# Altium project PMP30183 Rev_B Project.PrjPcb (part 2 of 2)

## Sheet PMP30183 Rev_B 2-Switch Forward Schematic.SchDoc: 2-Switch Forward
size 431 x 279 mm; Date: Not shown in title block; ApprovedBy: Not shown in title block; CheckedBy: Not shown in title block; Author: Not shown in title block; CompanyName: Not shown in title block; DrawnBy: R. Scibilia; Engineer: Not shown in title block; Organization: Not shown in title block; Address1: Not shown in title block; Address2: Not shown in title block; Address3: Not shown in title block; Address4: Not shown in title block; DocumentNumber: 1; Revision: Use project parameter SCH_Rev; SheetNumber: 2; SheetTotal: 2; PageSetup: Record=PageOptions¦CenterHorizontal=True¦CenterVertical=True¦PrintScale=1.00¦XCorrection=1.00¦YCorrection=1.00¦PrintKind=0¦BorderSize=5000000¦LeftOffset=0¦BottomOffset=0¦Orientation=2¦PaperLength=1000¦PaperWidth=1000¦Scale=100¦PaperSource=15¦PrintQuality=600¦MediaType=1¦DitherType=10¦PaperKind=Letter¦PrintScaleMode=1
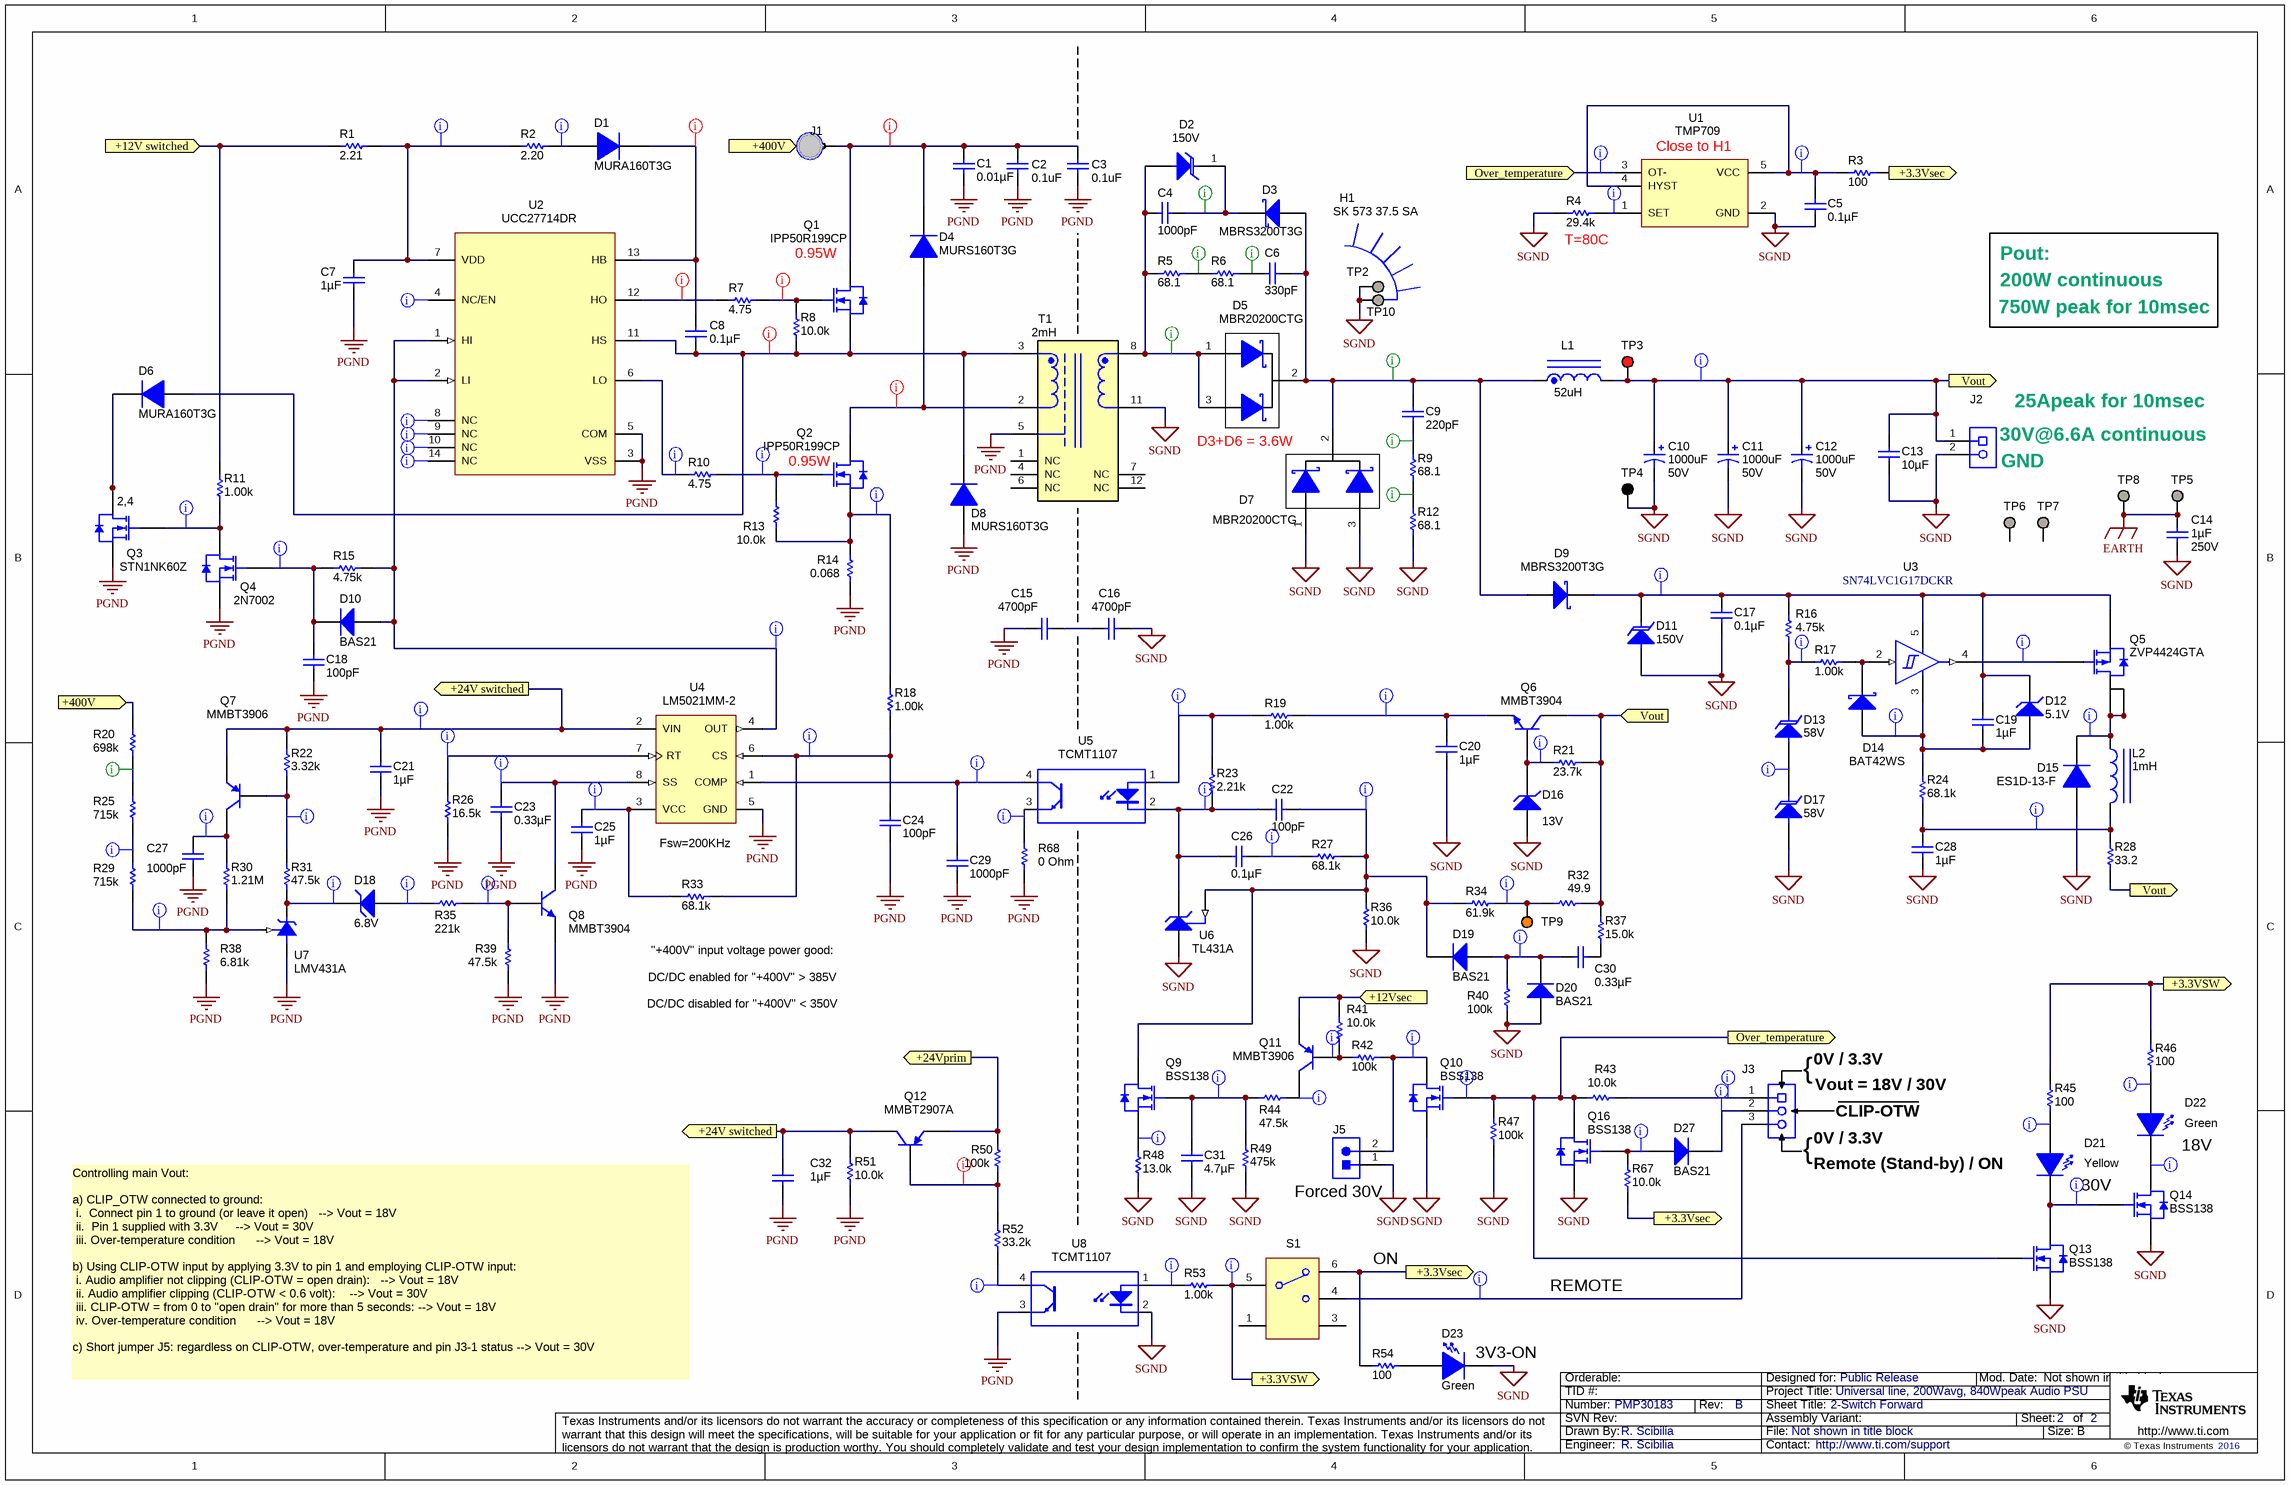
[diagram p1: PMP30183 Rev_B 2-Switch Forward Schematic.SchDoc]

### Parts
C1  ValueDisplayed: 0.01µF  [1206]  (hidden comment: C3216X7R2J103K)
C2  value 0.1uF  [1210]  (hidden comment: C3225X7T2J104K160AC)
C3  value 0.1uF  [1210]  (hidden comment: C3225X7T2J104K160AC)
C4  ValueDisplayed: 1000pF  [0805_HV]  (hidden comment: C0805C102JBRACTU)
C5  ValueDisplayed: 0.1µF  [0603]  (hidden comment: C1608X7R1H104K)
C6  ValueDisplayed: 330pF  [0603]  (hidden comment: GRM188R72E331KW07D)
C7  ValueDisplayed: 1µF  [0603]  (hidden comment: GRM188R71E105KA12D)
C8  ValueDisplayed: 0.1µF  [0603]  (hidden comment: C1608X7R1H104K)
C9  ValueDisplayed: 220pF  [1206]  (hidden comment: C3216C0G2J221J)
C10  value 1000uF  Value2: 50V  [CAPPR750W80D1600H3000]  (hidden comment: EKZM500ELL102ML25S)
C11  value 1000uF  Value2: 50V  [CAPPR750W80D1600H3000]  (hidden comment: EKZM500ELL102ML25S)
C12  value 1000uF  Value2: 50V  [CAPPR750W80D1600H3000]  (hidden comment: EKZM500ELL102ML25S)
C13  ValueDisplayed: 10µF  [1210_280]  (hidden comment: C3225X7R1H106M250AC)
C14  ValueDisplayed: 1µF  Value2: 250V  [2220_200]  (hidden comment: GRM55DR72E105KW01L)
C15  ValueDisplayed: 4700pF  [VY2_1250x500x1650]  (hidden comment: VY2472M49Y5US63V7)
C16  ValueDisplayed: 4700pF  [VY2_1250x500x1650]  (hidden comment: VY2472M49Y5US63V7)
C17  ValueDisplayed: 0.1µF  [1812]  (hidden comment: C1812C104KARACTU)
C18  ValueDisplayed: 100pF  [0603]  (hidden comment: C1608C0G1H101J)
C19  ValueDisplayed: 1µF  [0603]  (hidden comment: C1608X7R1E105K080AB)
C20  ValueDisplayed: 1µF  [0603]  (hidden comment: GRM188R71E105KA12D)
C21  ValueDisplayed: 1µF  [0805_HV]  (hidden comment: 885012207103)
C22  ValueDisplayed: 100pF  [0603]  (hidden comment: C1608C0G1H101J)
C23  ValueDisplayed: 0.33µF  [0603]  (hidden comment: C0603C334K4RACTU)
C24  ValueDisplayed: 100pF  [0603]  (hidden comment: C1608C0G1H101J)
C25  ValueDisplayed: 1µF  [0603]  (hidden comment: GRM188R71E105KA12D)
C26  ValueDisplayed: 0.1µF  [0603]  (hidden comment: C1608X7R1H104K)
C27  ValueDisplayed: 1000pF  [0603]  (hidden comment: GRM188R71H102KA01D)
C28  ValueDisplayed: 1µF  [0805_HV]  (hidden comment: 885012207103)
C29  ValueDisplayed: 1000pF  [0603]  (hidden comment: C1608X8R1H102K)
C30  ValueDisplayed: 0.33µF  [0805_HV]  (hidden comment: GRM219R71H334KA88D)
C31  ValueDisplayed: 4.7µF  [0805_HV]  (hidden comment: C2012X7R1E474K125AA)
C32  ValueDisplayed: 1µF  [0603]  (hidden comment: C1608X7R1E105K080AB)
D1  MURA160T3G  [SMA]
D2  value 150V  [SMB]  (hidden comment: SMBJ150A-13-F)
D3  MBRS3200T3G  [SMB]
D4  MURS160T3G  [SMB]
D5  MBR20200CTG  [TO-220AB]
D6  MURA160T3G  [SMA]
D7  MBR20200CTG  [TO-220AB]
D8  MURS160T3G  [SMB]
D9  MBRS3200T3G  [SMB]
D10  value BAS21  [SOT-23]  (hidden comment: BAS21-7-F)
D11  value 150V  [SMB]  (hidden comment: SMBJ150A-13-F)
D12  value 5.1V  [SOD-523]  (hidden comment: BZT52C5V1T-7)
D13  value 58V  [SMA]  (hidden comment: SMAJ58A)
D14  value BAT42WS  [sod-323]  (hidden comment: BAT42WS-7-F)
D15  ES1D-13-F  [SMA]
D16  value 13V  [sod-323]  (hidden comment: MMSZ5243BS-7-F)
D17  value 58V  [SMA]  (hidden comment: SMAJ58A)
D18  value 6.8V  [SOD-523]  (hidden comment: BZT52C6V8T-7)
D19  value BAS21  [SOT-23]  (hidden comment: BAS21-7-F)
D20  value BAS21  [SOT-23]  (hidden comment: BAS21-7-F)
D21  value Yellow  [LED_LTST-C170]  (hidden comment: LTST-C170KSKT)
D22  value Green  [LTST-C170KGKT_Green]  (hidden comment: LTST-C170KGKT)
D23  value Green  [LTST-C170KGKT_Green]  (hidden comment: LTST-C170KGKT)
D27  value BAS21  [SOT-23]  (hidden comment: BAS21-7-F)
H1  SK 573 37.5 SA  [FE_SK573_37_5]
J1  923345-01-C  [3M_923345-01-C]  (value not drawn)
J2  1732720  [Phoenix_1732720]  (value not drawn)
J3  39357-0003  [Molex_39357-0003]  (value not drawn)
J5  0022284023  [Molex_0022284023]  (value not drawn)
L1  value 52uH  [750315814]  (hidden comment: 750315814r01)
L2  ValueDisplayed: 1mH  [WE-PD_1280]  (hidden comment: 74477030)
Q1  IPP50R199CP  [TO-220AB]
Q2  IPP50R199CP  [TO-220AB]
Q3  STN1NK60Z  [SOT-223]
Q4  value 2N7002  [SOT-23]  (hidden comment: 2N7002E-T1-E3)
Q5  ZVP4424GTA  [SOT-223]
Q6  MMBT3904  [SOT-23]
Q7  MMBT3906  [SOT-23]
Q8  MMBT3904  [SOT-23]
Q9  BSS138  [SOT-23]
Q10  BSS138  [SOT-23]
Q11  MMBT3906  [SOT-23]
Q12  MMBT2907A  [SOT-23]
Q13  BSS138  [SOT-23]
Q14  BSS138  [SOT-23]
Q16  BSS138  [SOT-23]
R1  ValueDisplayed: 2.21  [0805_HV]  (hidden comment: CRCW08052R21FKEA)
R2  value 2.20  [1206]  (hidden comment: RC1206FR-072R2L)
R3  ValueDisplayed: 100  [0603]  (hidden comment: CRCW0603100RFKEA)
R4  ValueDisplayed: 29.4k  [0603]  (hidden comment: CRCW060329K4FKEA)
R5  ValueDisplayed: 68.1  [2512]  (hidden comment: CRCW251268R1FKEG)
R6  ValueDisplayed: 68.1  [2512]  (hidden comment: CRCW251268R1FKEG)
R7  ValueDisplayed: 4.75  [0805_HV]  (hidden comment: RC0805FR-074R75L)
R8  value 10.0k  [0603]  (hidden comment: CRCW060310K0FKEA)
R9  ValueDisplayed: 68.1  [2512]  (hidden comment: CRCW251268R1FKEG)
R10  ValueDisplayed: 4.75  [0805_HV]  (hidden comment: RC0805FR-074R75L)
R11  ValueDisplayed: 1.00k  [0603]  (hidden comment: CRCW06031K00FKEA)
R12  ValueDisplayed: 68.1  [2512]  (hidden comment: CRCW251268R1FKEG)
R13  value 10.0k  [0603]  (hidden comment: CRCW060310K0FKEA)
R14  ValueDisplayed: 0.068  [2512]  (hidden comment: 2-2176057-1)
R15  ValueDisplayed: 4.75k  [0603]  (hidden comment: CRCW06034K75FKEA)
R16  ValueDisplayed: 4.75k  [1206]  (hidden comment: CRCW12064K75FKEA)
R17  ValueDisplayed: 1.00k  [0603]  (hidden comment: CRCW06031K00FKEA)
R18  ValueDisplayed: 1.00k  [0603]  (hidden comment: CRCW06031K00FKEA)
R19  ValueDisplayed: 1.00k  [0603]  (hidden comment: CRCW06031K00FKEA)
R20  value 698k  [1206]  (hidden comment: CRCW1206698KFKEA)
R21  ValueDisplayed: 23.7k  [0603]  (hidden comment: CRCW060323K7FKEA)
R22  ValueDisplayed: 3.32k  [0603]  (hidden comment: CRCW06033K32FKEA)
R23  value 2.21k  [0603]  (hidden comment: CRCW06032K21FKEA)
R24  ValueDisplayed: 68.1k  [2010]  (hidden comment: CRCW201068K1FKEF)
R25  value 715k  [1206]  (hidden comment: CRCW1206715KFKEA)
R26  ValueDisplayed: 16.5k  [0603]  (hidden comment: CRCW060316K5FKEA)
R27  ValueDisplayed: 68.1k  [0603]  (hidden comment: CRCW060368K1FKEA)
R28  ValueDisplayed: 33.2  [2512]  (hidden comment: CRCW251233R2FKEG)
R29  value 715k  [1206]  (hidden comment: CRCW1206715KFKEA)
R30  ValueDisplayed: 1.21M  [0603]  (hidden comment: CRCW06031M21FKEA)
R31  ValueDisplayed: 47.5k  [0603]  (hidden comment: CRCW060347K5FKEA)
R32  value 49.9  [0603]  (hidden comment: CRCW060349R9FKEA)
R33  ValueDisplayed: 68.1k  [0603]  (hidden comment: CRCW060368K1FKEA)
R34  ValueDisplayed: 61.9k  [0603]  (hidden comment: CRCW060361K9FKEA)
R35  ValueDisplayed: 221k  [0603]  (hidden comment: CRCW0603221KFKEA)
R36  value 10.0k  [0603]  (hidden comment: CRCW060310K0FKEA)
R37  ValueDisplayed: 15.0k  [0603]  (hidden comment: RC0603FR-0715KL)
R38  value 6.81k  [0603]  (hidden comment: CRCW06036K81FKEA)
R39  ValueDisplayed: 47.5k  [0603]  (hidden comment: CRCW060347K5FKEA)
R40  ValueDisplayed: 100k  [0603]  (hidden comment: CRCW0603100KFKEA)
R41  value 10.0k  [0603]  (hidden comment: CRCW060310K0FKEA)
R42  ValueDisplayed: 100k  [0603]  (hidden comment: CRCW0603100KFKEA)
R43  value 10.0k  [0603]  (hidden comment: CRCW060310K0FKEA)
R44  ValueDisplayed: 47.5k  [0603]  (hidden comment: RC0603FR-0747K5L)
R45  ValueDisplayed: 100  [0603]  (hidden comment: CRCW0603100RFKEA)
R46  ValueDisplayed: 100  [0603]  (hidden comment: CRCW0603100RFKEA)
R47  ValueDisplayed: 100k  [0603]  (hidden comment: CRCW0603100KFKEA)
R48  ValueDisplayed: 13.0k  [0603]  (hidden comment: RC0603FR-0713KL)
R49  ValueDisplayed: 475k  [0603]  (hidden comment: RC0603FR-07475KL)
R50  ValueDisplayed: 100k  [0603]  (hidden comment: CRCW0603100KFKEA)
R51  value 10.0k  [0603]  (hidden comment: CRCW060310K0FKEA)
R52  ValueDisplayed: 33.2k  [0603]  (hidden comment: CRCW060333K2FKEA)
R53  ValueDisplayed: 1.00k  [0603]  (hidden comment: CRCW06031K00FKEA)
R54  ValueDisplayed: 100  [0603]  (hidden comment: CRCW0603100RFKEA)
R67  value 10.0k  [0603]  (hidden comment: CRCW060310K0FKEA)
R68  0 Ohm  [0603]
S1  200USP1T1A1M2RE  [SW_200USP1T1A1M2]  (value not drawn)
T1  ValueDisplayed: 2mH  [Wurth_750315800]  (hidden comment: 750315800)
TP2  TESTPOINT  [PAD_115mil-80milhole]  (value not drawn)  (no BOM)
TP3  5000  [Keystone5000]  (value not drawn)
TP4  5001  [Keystone5001]  (value not drawn)
TP5  TESTPOINT  [PAD_115mil-80milhole]  (value not drawn)  (no BOM)
TP6  TESTPOINT  [PAD_115mil-80milhole]  (value not drawn)  (no BOM)
TP7  TESTPOINT  [PAD_115mil-80milhole]  (value not drawn)  (no BOM)
TP8  TESTPOINT  [PAD_115mil-80milhole]  (value not drawn)  (no BOM)
TP9  5003  [Keystone5003]  (value not drawn)
TP10  TESTPOINT  [PAD_115mil-80milhole]  (value not drawn)  (no BOM)
U1  value TMP709  [MF05A_N]  (hidden comment: DS90LT012AHMF/NOPB)
U2  UCC27714DR  [D0014A_N]
U3  SN74LVC1G17DCKR  [DCK0005A_N]
U4  value LM5021MM-2  [MUA08A_N]  (hidden comment: LM5021MMX-2)
U5  TCMT1107  [SOP-4]
U6  value TL431A  [DBZ0003A_N]  (hidden comment: TL431AIDBZR)
U7  value LMV431A  [MF03A_N]  (hidden comment: LMV431AIMF)
U8  TCMT1107  [SOP-4]

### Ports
+3.3Vsec, +3.3VSW, +12V switched, +12Vsec, +24V switched, +24Vprim, +400V, Over_temperature, Vout

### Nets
EARTH: C14.1 TP5.1 TP8.1
PGND: C1.2 C2.2 C3.2 C7.2 C15.1 C18.2 C21.2 C23.2 C24.2 C25.2 C27.2 C29.2 C32.2 D8.2(A) Q3.3(S) Q4.2(S) Q8.2(E) R14.1 R26.1 R38.1 R39.1 R51.2 R68.1 T1.5 U2.3(VSS) U2.5(COM) U4.5(GND) U7.3(A) U8.3(E)
SGND: C5.2 C10.2(-) C11.2(-) C12.2(-) C13.2 C14.2 C16.2 C17.2 C20.2 C28.2 C31.2 D7.1(A) D7.3(A) D11.2(A) D15.2(A) D16.2(A) D17.2(A) D20.1(A) D23.2(K) J2.2 J5.1 Q10.2(S) Q13.2(S) Q14.2(S) Q16.2(S) R4.2 R12.1 R36.1 R40.2 R47.1 R48.1 R49.1 T1.11 TP2.1 TP4.1 TP10.1 U1.2(GND) U6.3(ANODE) U8.2(K)
+3.3Vsec: R3.2 R54.1 R67.2 S1.6 ; port +3.3Vsec
+3.3VSW: R45.1 R46.1 R53.2 S1.5(COM) ; port +3.3VSW
+12V switched: R1.1 R11.2 ; port +12V switched
+12Vsec: Q11.2(E) R41.1 ; port +12Vsec
+24V switched: C21.1 C32.1 Q7.2(E) Q12.3(C) R22.2 R51.1 U4.2(VIN) ; port +24V switched
+24Vprim: Q12.2(E) R50.2 ; port +24Vprim
+400V: J1.1 R20.2 ; port +400V
Over_temperature: Q10.1(G) Q13.1(G) Q16.3(D) R43.2 R47.2 U1.3(OT-) ; port Over_temperature
Vout: C10.1(+) C11.1(+) C12.1(+) C13.1 J2.1 L1.2 Q6.3(C) R21.1 R28.1 R32.1 R37.2 TP3.1 ; port Vout
NetC1_1: C1.1 C2.1 C3.1 D4.1(K) J1.2 Q1.2(D)
NetC4_1: C4.1 D2.1(K) D3.1(K)
NetC4_2: C4.2 D2.2(A) D5.1(A) D5.3(A) R5.1 T1.8
NetC5_1: C5.1 R3.1 U1.4(HYST) U1.5(VCC)
NetC6_1: C6.1 C9.1 D3.2(A) D5.2(K) D7.2(K) D9.2(A) L1.1
NetC6_2: C6.2 R6.2
NetC7_1: C7.1 R1.2 R2.2 U2.7(VDD)
NetC8_1: C8.1 D6.2(A) D8.1(K) Q1.3(S) R8.2 T1.3 U2.11(HS)
NetC8_2: C8.2 D1.1(K) U2.13(HB)
NetC9_2: C9.2 R9.2
NetC15_2: C15.2 C16.1
NetC17_1: C17.1 C19.1 D9.1(K) D11.1(K) D12.1(K) Q5.3(S) R16.2 U3.5(VCC)
NetC18_1: C18.1 D10.3(K) Q4.1(G) R15.1
NetC19_2: C19.2 D12.2(A) D14.2(A) R24.2 U3.3(GND)
NetC20_1: C20.1 Q6.2(E) R19.2
NetC22_1: C22.1 D19.3(K) Q9.3(D) R27.1 R34.1 R36.2 U6.2(REF)
NetC22_2: C22.2 C26.2 R23.1 U5.2(K) U6.1(CATHODE)
NetC23_1: C23.1 Q8.3(C) U4.8(SS)
NetC24_1: C24.1 R18.1 R33.2 U4.6(CS)
NetC25_1: C25.1 R33.1 U4.3(VCC)
NetC26_1: C26.1 R27.2
NetC27_1: C27.1 Q7.3(C) R30.2
NetC28_1: C28.1 L2.2 R24.1 R28.2
NetC29_1: C29.1 U4.1(COMP) U5.4(C)
NetC30_1: C30.1 R37.1
NetC30_2: C30.2 D19.1(A) D20.3(K) R40.1
NetC31_1: C31.1 Q9.1(G) R44.2 R49.2
NetD1_2: D1.2(A) R2.1
NetD4_2: D4.2(A) Q2.2(D) T1.2
NetD6_1: D6.1(K) Q3.2(D) Q3.4(D)
NetD10_1: D10.1(A) R15.2 U2.1(HI) U2.2(LI) U4.4(OUT)
NetD13_1: D13.1(K) R16.1 R17.1
NetD13_2: D13.2(A) D17.1(K)
NetD14_1: D14.1(K) R17.2 U3.2(A)
NetD15_1: D15.1(K) L2.1 Q5.2(D) Q5.4(D)
NetD16_1: D16.1(K) Q6.1(B) R21.2
NetD18_1: D18.1(K) R31.1 U7.2(K)
NetD18_2: D18.2(A) R35.1
NetD21_1: D21.1(A) R45.2
NetD21_2: D21.2(K) Q13.3(D) Q14.1(G)
NetD22_1: D22.1(A) R46.2
NetD22_2: D22.2(K) Q14.3(D)
NetD23_1: D23.1(A) R54.2
NetD27_1: D27.1(A) Q16.1(G) R67.1
NetD27_3: D27.3(K) J3.2
NetJ3_1: J3.1 R43.1
NetJ3_3: J3.3 S1.4
NetJ5_2: J5.2 Q10.3(D) R42.1
NetQ1_1: Q1.1(G) R7.2 R8.1
NetQ2_1: Q2.1(G) R10.2 R13.1
NetQ2_3: Q2.3(S) R13.2 R14.2 R18.2
NetQ3_1: Q3.1(G) Q4.3(D) R11.1
NetQ5_1: Q5.1(G) U3.4(Y)
NetQ7_1: Q7.1(B) R22.1 R31.2
NetQ8_1: Q8.1(B) R35.2 R39.2
NetQ9_2: Q9.2(S) R48.2
NetQ11_1: Q11.1(B) R41.2 R42.2
NetQ11_3: Q11.3(C) R44.1
NetQ12_1: Q12.1(B) R50.1 R52.2
NetR4_1: R4.1 U1.1(SET)
NetR5_2: R5.2 R6.1
NetR7_1: R7.1 U2.12(HO)
NetR9_1: R9.1 R12.2
NetR10_1: R10.1 U2.6(LO)
NetR19_1: R19.1 R23.2 U5.1(A)
NetR20_1: R20.1 R25.2
NetR25_1: R25.1 R29.2
NetR26_2: R26.2 U4.7(RT)
NetR29_1: R29.1 R30.1 R38.2 U7.1(REF)
NetR32_2: R32.2 R34.2 TP9.1
NetR52_1: R52.1 U8.4(C)
NetR53_1: R53.1 U8.1(A)
NetR68_2: R68.2 U5.3(E)

Not connected (* = marked no-connect by the designer): S1 1 3; T1 1(NC) 4(NC) 6(NC) 7(NC) 12(NC); TP6 1; TP7 1; U2 4(NC/EN) 8(NC) 9(NC) 10(NC) 14(NC)

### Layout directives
rule Undefined; rule Clearance Constraint [Clearance = 10mil]: (no net found under the mark), +3.3VSW, +24V switched, NetC5_1, NetC7_1, NetC17_1, NetC18_1, NetC19_2, NetC20_1, NetC22_1, NetC22_2, NetC23_1, NetC24_1, NetC25_1, NetC26_1, NetC27_1, NetC28_1, NetC29_1, NetC30_2, NetC31_1, NetD1_2, NetD10_1, NetD13_1, NetD13_2, NetD15_1, NetD16_1, NetD18_1, NetD18_2, NetD21_1, NetD21_2, NetD22_1, NetD22_2, NetD27_1, NetD27_3, NetJ3_1, NetJ3_3, NetJ5_2, NetQ2_1, NetQ2_3, NetQ3_1, NetQ5_1, NetQ7_1, NetQ8_1, NetQ9_2, NetQ11_3, NetQ12_1, NetR4_1, NetR10_1, NetR19_1, NetR25_1, NetR26_2, NetR29_1, NetR32_2, NetR52_1, NetR53_1, NetR68_2, NetU2_4, NetU2_8, NetU2_9, NetU2_10, NetU2_14, Over_temperature, Vout
rule Undefined; rule Clearance Constraint [Clearance = 20mil]: NetC4_1, NetC4_2, NetC6_1, NetC6_2, NetC9_2, NetR5_2, NetR9_1, NetR20_1
rule Undefined; rule Clearance Constraint [Clearance = 30mil]: NetC1_1, NetC8_1, NetC8_2, NetD4_2, NetQ1_1, NetR7_1

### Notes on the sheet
- (near U1) Close to H1
- (near Q1) 0.95W
- (near R4) T=80C
- Pout:
- 200W continuous
- 750W peak for 10msec
- D3+D6 = 3.6W
- 30V@6.6A continuous
- 25Apeak for 10msec
- (near Q2) 0.95W
- GND
- (near U4) Fsw=200KHz
- (near R33) "+400V" input voltage power good:
- DC/DC enabled for "+400V" > 385V
- DC/DC disabled for "+400V" < 350V
- (near J3) {
- (near J3) 0V / 3.3V
- CLIP-OTW
- (near J3) Vout = 18V / 30V
- Remote (Stand-by) / ON
- 18V
- (near J5) Forced 30V
- (near Q14) 30V
- ON
- REMOTE
- Controlling main Vout:
  a) CLIP_OTW connected to ground:
  i.  Connect pin 1 to ground (or leave it open)			--> Vout = 18V
  ii.  Pin 1 supplied with 3.3V					--> Vout = 30V
  iii. Over-temperature condition 					--> Vout = 18V
  b) Using CLIP-OTW input by applying 3.3V to pin 1 and employing CLIP-OTW input:
  i. Audio amplifier not clipping (CLIP-OTW = open drain): 		--> Vout = 18V
  ii. Audio amplifier clipping (CLIP-OTW < 0.6 volt): 			--> Vout = 30V
  iii. CLIP-OTW = from 0 to "open drain" for more than 5 seconds:	--> Vout = 18V
  iv. Over-temperature condition 					--> Vout = 18V
  c) Short jumper J5: regardless on CLIP-OTW, over-temperature and pin J3-1 status --> Vout = 30V
- (near D23) 3V3-ON

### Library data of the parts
C1 = C3216X7R2J103K: CAP, CERM, 0.01 µF, 630 V, +/- 10%, X7R, 1206; Manufacturer: TDK; Polarized: N; CompType: Capacitor; Value: 0.01uF; U/M: EA; Cap_F: 0.00000001; Tolerance_%: 10; ESR_ohm: 0.0923; Value1: 0.0923 ohm; VDC_V: 630; Value2: 630V; TaMin_C: -55; TaMax_C: 125; AEC Category: Q200
C2 C3 = GRM32DR72J473KW01L: CAP, CERM, 0.1 µF, 630 V, +/- 10%, X7T 1210; Manufacturer: TDK; Polarized: N; CompType: Capacitor; ValueDisplayed: 0.1µF; U/M: EA; Cap_F: 0.000000047; Tolerance_%: 10; Value1: Unknown; VDC_V: 630; Value2: 630V; TaMin_C: -55; TaMax_C: 125
C4 = C0805C102JBRACTU: CAP, CERM, 1000 pF, 630 V, +/- 5%, X7R, 0805; Manufacturer: Kemet; Polarized: N; CompType: Capacitor; Value: 1000pF; U/M: EA; Cap_F: 0.000000001; Tolerance_%: 5; Value1: Unknown; VDC_V: 630; Value2: 630V; TaMin_C: -55; TaMax_C: 125; Cap_Case: 0805; AEC Category: Q200
C5 C8 C26 = C1608X7R1H104K: CAP, CERM, 0.1uF, 50V, +/-10%, X7R, 0603; Manufacturer: TDK; Polarized: N; CompType: Capacitor; U/M: EA; Cap_F: 0.0000001; Tolerance_%: 10; ESR_Ohm: 0.017; Value1: 0.017 ohm; VDC_V: 50; TaMin_C: -55; TaMax_C: 125
C6 = GRM188R72E331KW07D: CAP, CERM, 330 pF, 250 V, +/- 10%, X7R, 0603; Manufacturer: MuRata; Polarized: N; CompType: Capacitor; Value: 330pF; U/M: EA; Cap_F: 0.00000000033; Tolerance_%: 10; Value1: Unknown; VDC_V: 250; Value2: 250V; TaMin_C: -55; TaMax_C: 125; AEC Category: Q200
C7 C20 C25 = GRM188R71E105KA12D: CAP, CERM, 1uF, 25V, +/-10%, X7R, 0603; Manufacturer: MuRata; Polarized: N; CompType: Capacitor; U/M: EA; Cap_F: 0.000001; Tolerance_%: 10; VDC_V: 25; TaMin_C: -55; TaMax_C: 125
C9 = C3216C0G2J221J: CAP, CERM, 220 pF, 630 V, +/- 5%, C0G/NP0, 1206; Manufacturer: TDK; Polarized: N; CompType: Capacitor; Value: 220pF; U/M: EA; Cap_F: 0.00000000022; Tolerance_%: 5; ESR_ohm: 0.1029; Value1: 0.1029 ohm; VDC_V: 630; Value2: 630V; TaMin_C: -55; TaMax_C: 125; AEC Category: Q200
C10-C12 = 400KXW100MEFC16X30: CAP, AL, 1000 µF, 50 V, +/- 20%, TH; Manufacturer: Nippon Chemi-Con; Polarized: Y; CompType: Capacitor; ValueDisplayed: 1000µF; U/M: EA; Cap_F: 0.0001; Tolerance_%: 20; Value1: Unknown; VDC_V: 400; IRMS_A: 0.58; TaMin_C: -25; TaMax_C: 105; Cap_Case: RCAP, 16x25mm
C13 = C3225X7R1H106M250AC: CAP, CERM, 10 µF, 50 V, +/- 20%, X7R, 1210; Manufacturer: TDK; Polarized: N; CompType: Capacitor; Value: 10uF; U/M: EA; Cap_F: 0.00001; Tolerance_%: 20; Value1: Unknown; VDC_V: 50; Value2: 50V; TaMin_C: -55; TaMax_C: 125; Cap_Case: 1210
C14 = GRM55DR72E105KW01L: CAP, CERM, 1 µF, 250 V, +/- 10%, X7R, 2220; Manufacturer: MuRata; Polarized: N; CompType: Capacitor; Value: 1uF; U/M: EA; Cap_F: 0.000001; Tolerance_%: 10; ESR_ohm: 0.007086; Value1: 0.007086 ohm; VDC_V: 250; IRMS_A: 2.0605; TaMin_C: -55; TaMax_C: 125; Cap_Case: 2220; SizeArea_mm2: 28.5; SizeAreaWB_mm2: 53.9; SizeX_mm: 5.7; SizeY_mm: 5; SizeZ_mm: 2; AEC Category: Q200
C15 C16 = VY2472M49Y5US63V7: CAP, CERM, 4700 pF, 440 V, +/- 20%, Y5U, TH, 12.5x5mm; Manufacturer: Vishay-Bccomponents; Polarized: N; CompType: Capacitor; Value: 4700pF; U/M: EA; Cap_F: 0.0000000047; Tolerance_%: 20; Value1: Unknown; VDC_V: 440; Value2: 440V; TaMin_C: -40; TaMax_C: 125; Cap_Case: 12.5x5x16.5
C17 = C1812C104KARACTU: CAP, CERM, 0.1 µF, 250 V, +/- 10%, X7R, 1812; Manufacturer: Kemet; Polarized: N; CompType: Capacitor; Value: 0.1uF; U/M: EA; Cap_F: 0.0000001; Tolerance_%: 10; Value1: Unknown; VDC_V: 250; Value2: 250V; TaMin_C: -55; TaMax_C: 125
C18 C22 C24 = C1608C0G1H101J: CAP, CERM, 100 pF, 50 V, +/- 5%, C0G/NP0, 0603; Manufacturer: TDK; Polarized: N; CompType: Capacitor; Value: 100pF; U/M: EA; Cap_F: 0.0000000001; Tolerance_%: 5; ESR_ohm: 0.1679; Value1: 0.1679 ohm; VDC_V: 50; Value2: 50V; TaMin_C: -55; TaMax_C: 125; AEC Category: Q200
C19 C32 = C1608X7R1E105K080AB: CAP, CERM, 1uF, 25V, +/-10%, X7R, 0603; Manufacturer: TDK; Polarized: N; CompType: Capacitor; U/M: EA; Cap_F: 0.000001; Tolerance_%: 10; Value1: Unknown; VDC_V: 25; TaMin_C: -55; TaMax_C: 125
C21 C28 = 885012207103: CAP, CERM, 1 µF, 50 V, +/- 10%, X7R, 0805; Manufacturer: Wurth Elektronik; Polarized: N; CompType: Capacitor; Value: 1uF; U/M: EA; Cap_F: 0.000001; Tolerance_%: 10; Value1: Unknown; VDC_V: 50; Value2: 50V; TaMin_C: -55; TaMax_C: 125; Cap_Case: 0805; AEC Category: Q200
C23 = C0603C334K4RACTU: CAP, CERM, 0.33 µF, 16 V, +/- 10%, X7R, 0603; Manufacturer: Kemet; Polarized: N; CompType: Capacitor; Value: 0.33uF; U/M: EA; Cap_F: 0.00000033; Tolerance_%: 10; Value1: Unknown; VDC_V: 16; Value2: 16V; TaMin_C: -55; TaMax_C: 125; AEC Category: Q200
C27 = GRM188R71H102KA01D: CAP, CERM, 1000 pF, 50 V, +/- 10%, X7R, 0603; Manufacturer: MuRata; Polarized: N; CompType: Capacitor; Value: 1000pF; U/M: EA; Cap_F: 0.000000001; Tolerance_%: 10; Value1: Unknown; VDC_V: 50; Value2: 50V; TaMin_C: -55; TaMax_C: 125; SizeArea_mm2: 1.28; SizeAreaWB_mm2: 4.68; SizeX_mm: 1.6; SizeY_mm: 0.8; SizeZ_mm: 1; AEC Category: Q200
C29 = C1608X8R1H102K: CAP, CERM, 1000 pF, 50 V, +/- 10%, X8R, 0603; Manufacturer: TDK; Polarized: N; CompType: Capacitor; Value: 1000pF; U/M: EA; Cap_F: 0.000000001; Tolerance_%: 10; ESR_ohm: 0.1942; Value1: 0.1942 ohm; VDC_V: 50; Value2: 50V; TaMin_C: -55; TaMax_C: 150; AEC Category: Q200
C30 = GRM219R71H334KA88D: CAP, CERM, 0.33 µF, 50 V, +/- 10%, X7R, 0805; Manufacturer: MuRata; Polarized: N; CompType: Capacitor; Value: 0.33uF; U/M: EA; Cap_F: 0.00000033; Tolerance_%: 10; Value1: Unknown; VDC_V: 50; Value2: 50V; TaMin_C: -55; TaMax_C: 125; Cap_Case: 0805
C31 = C2012X7R1E474K125AA: CAP, CERM, 4.7 µF, 25 V, +/- 10%, X7R, 0805; Manufacturer: TDK; Polarized: N; CompType: Capacitor; Value: 4.7uF; U/M: EA; Cap_F: 0.0000047; Tolerance_%: 10; Value1: Unknown; VDC_V: 25; Value2: 25V; TaMin_C: -55; TaMax_C: 125; Cap_Case: 0805; SizeArea_mm2: 2.5; SizeAreaWB_mm2: 6.75; SizeX_mm: 2; SizeY_mm: 1.25; SizeZ_mm: 1.45; AEC Category: Q200
D1 D6 = MURA160T3G: Diode, Ultrafast, 600 V, 1 A, AEC-Q101, SMA; Manufacturer: ON Semiconductor; U/M: EA; Vf_V: 1.05; Value: 600V; Value1: 1A; Value2: 1.05V; Io_A: 1; Vr_V: 600; TJmax_C: 175; AEC Category: Q101; AEC Qualified: Y
D2 D11 = SMBJ150A-13-F: Diode, TVS, Uni, 150 V, 600 W, SMB; Manufacturer: Diodes Inc.; U/M: EA; Power_W: 5; Vr_V: 150; Value1: 5W; AEC Category: Q101
D3 D9 = MBRS3200T3G: Diode, Schottky, 200 V, 3 A, SMB; Manufacturer: ON Semiconductor; U/M: EA; Vf_V: 0.84; Value: 200V; Value1: 3A; Value2: 0.84V; Io_A: 3; Vr_V: 200; TJmax_C: 175; RJC_CperW: 62
D4 D8 = MURS160T3G: Diode, Ultrafast, 600 V, 2 A, SMB; Manufacturer: ON Semiconductor; U/M: EA; Vf_V: 1.25; Value: 600V; Value1: 2A; Value2: 1.25V; Io_A: 2; Vr_V: 600; TJmax_C: 175
D5 D7 = VS-48CTQ060PBF: Diode, Schottky, 200 V, 20 A, TH; Manufacturer: Microsemi; SymbolCreator: a0411947; U/M: EA; Vf_V: 0.58; Value1: 20A; Value2: 0.58V; Io_A: 20; Vr_V: 60; TJmax_C: 150
D10 D19 D20 D27 = BAS21-7-F: Diode, Switching, 200 V, 0.2 A, SOT-23; Manufacturer: Diodes Inc.; U/M: EA; Vf_V: 1.25; Value1: 0.2A; Value2: 1.25V; Io_A: 0.2; Vr_V: 200; TJmax_C: 150; RJC_CperW: 500
D12 = BZT52C5V1T-7: Diode, Zener, 5.1 V, 300 mW, SOD-523; Manufacturer: Diodes Inc.; SymbolCreator: a0412235; U/M: EA; Power_W: 0.3; Vz_V: 5.1; Value1: 0.3W; RJA_CperW: 417; AEC Category: Q101
D13 D17 = SMAJ58A: Diode, TVS, Uni, 58 V, 400 W, SMA; Manufacturer: Diodes Inc.; U/M: EA; Power_W: 400; Vr_V: 58; Value1: 400W; AEC Category: Q101
D14 = BAT42WS-7-F: Diode, Schottky, 30 V, 0.2 A, SOD-323; Manufacturer: Diodes Inc.; U/M: EA; Vf_V: 1; Value1: 0.2A; Value2: 1V; Io_A: 0.2; Vr_V: 30; AEC Category: Q101
D15 = ES1D-13-F: Diode, Ultrafast, 200 V, 1 A, SMA; Manufacturer: Diodes Inc.; U/M: EA; Vf_V: 0.92; Value: 200V; Value1: 1A; Value2: 0.92V; Io_A: 1; Vr_V: 200; TJmax_C: 150; RJC_CperW: 25; AEC Category: Q101
D16 = MMSZ5243BS-7-F: Diode, Zener, 13 V, 200 mW, SOD-323; Manufacturer: Diodes Inc.; SymbolCreator: a0412235; U/M: EA; Power_W: 0.2; Vz_V: 13; Value1: 0.2W; RJA_CperW: 350
D18 = BZT52C6V8T-7: Diode, Zener, 6.8 V, 300 mW, SOD-523; Manufacturer: Diodes Inc.; SymbolCreator: a0412235; U/M: EA; Power_W: 0.3; Vz_V: 6.8; Value1: 0.3W; RJA_CperW: 417; AEC Category: Q101
D21 = LTST-C170KSKT: LED, Yellow , SMD; Manufacturer: Lite-On; Type: AlInGaP; Vf_V: 2; Value2: 2V; Io_A: 0.02; Value1: W; SizeAreaWB_mm2: 6.75; SizeArea_mm2: 2.5; SizeY_mm: 1.25; SizeZ_mm: 1.2; U/M: EA
D22 D23 = LTST-C170KGKT: LED, Green, SMD; Manufacturer: Lite-On; Type: AlInGaP; Vf_V: 2; Value2: 2V; Io_A: 0.02; Value1: W; U/M: EA
H1 = SK 573 37.5 SA: Heat Sink, 25x30x37.5mm, for THFU 1-3+6+7, profile threads; Manufacturer: Fischer Elektronik; SymbolCreator: a0412235
J1 = 923345-01-C: Jumper Wire, 100mil spacing, pkg of 200, TH; Manufacturer: 3M; SymbolCreator: Altium; U/M: EA
J2 = 1732720: Terminal Block, 2x1, 7.62mm, TH; Manufacturer: Phoenix Contact; SymbolCreator: a0412235; U/M: EA
J3 = 39357-0003: Terminal Block, 3.5 mm, 3x1, Tin, TH; Manufacturer: Molex; SymbolCreator: a0412235; U/M: EA
J5 = 0022284023: Header, 2.54mm, 2x1, Tin, TH; Manufacturer: Molex; SymbolCreator: a0412235; Pitch_mm: 2.54; Gender: Male; Shrouded: N; Row_Count: 1; Current_A: 4; Voltage_V: 250; Cert_UL: Y
L1 = 750315814: Inductor, Toroid, 52 µH, 0.052 ohm, TH; Manufacturer: Wurth Elektronik; SymbolCreator: a0412235; ValueDisplayed: 52µH; Ind_H: 22.0E-6; DCR_ohm: 0.052; Value2: A; AEC Category: Q200; AEC Qualified: N
L2 = 74477030: Inductor, Shielded Drum Core, Ferrite, 1 mH, 0.6 A, 1.82 ohm, SMD; Manufacturer: Wurth Elektronik; Value: 1mH; Ind_H: 1.0E-3; Imax_A: 0.6; Irms: 0.6A @ 40C rise; Isat: 0.7A @ 10% inductance drop; DCR_ohm: 1.82; Value2: 0.6A; SizeAreaWB_mm2: 196; SizeArea_mm2: 144; SizeX_mm: 12; SizeZ_mm: 8; AEC Category: Q200
Q1 Q2 = IPP50R199CP: MOSFET, N-CH, 550 V, 17 A, TO-220AB; Manufacturer: Infineon Technologies; Alternate Manufacturer: None; U/M: EA; ChType: N; Value: 550V; VdsMax_V: 550; Value1: ? ohm; Rdson45_ohm: 0; Value2: 34 nC; QgTyp_nC: 34; Vgs_V: 20; IdsMax_A: 17
Q3 = FQT7N10LTF: MOSFET, N-CH, 600 V, 300 mA, SOT-223; Manufacturer: ST; Alternate Manufacturer: None; U/M: EA; ChType: N; VdsMax_V: 600; Value1: 8.5 ohm; Rdson45_ohm: 8.5; Value2: 4.9 nC; QgTyp_nC: 4.9; Vgs_V: 20; IdsMax_A: 1.2; AEC Category: Q101
Q4 = 2N7002E-T1-E3: MOSFET, N-CH, 60 V, 0.24 A, SOT-23; Manufacturer: Vishay-Siliconix; Alternate Manufacturer: None; U/M: EA; ChType: N; VdsMax_V: 60; Value1: 1.8 ohm; Rdson45_ohm: 1.8; Value2: 0.4 nC; QgTyp_nC: 0.4; Vgs_V: 20; IdsMax_A: 0.24; AEC Category: Q101
Q5 = ZVP4424GTA: MOSFET, P-CH, -240 V, -0.48 A, SOT-223; Manufacturer: Diodes Inc.; Alternate Manufacturer: None; SymbolCreator: a0799628; U/M: EA; ChType: P; Value: -240V; Value1: ? ohm; Value2: ? nC; Vgs_V: -40; AEC Category: Q101; AEC Qualified: N
Q6 Q8 = MMBT3904, Fairchild Semiconductor: Transistor, NPN, 40 V, 0.2 A, SOT-23; CompType: BJT; PNP: 0; NPN: 1; Vceo_V: 40; Vcesat1_V: 0.2; Value: 40 V; Value1: 0.2 A; HfeMax: 300; TaMin_C: -55; TaMax_C: 150; U/M: EA
Q7 Q11 = MMBT3906, Fairchild Semiconductor: Transistor, PNP, 40V, 0.2A, SOT-23; CompType: BJT; PNP: 1; NPN: 0; Vceo_V: 40; Vcesat1_V: 0.25; Value: 0.25V; IcRated_A: 0.2; HfeMax: 300; TaMin_C: -55; TaMax_C: 150; U/M: EA
Q9 Q10 Q13 Q14 Q16 = BSS138: MOSFET, N-CH, 50 V, 0.22 A, SOT-23; Manufacturer: Fairchild Semiconductor; Alternate Manufacturer: None; U/M: EA; ChType: N; Value: 50V; VdsMax_V: 50; Value1: 6 ohm; Rdson45_ohm: 6; Value2: 1.7 nC; QgTyp_nC: 1.7; Vgs_V: 20; IdsMax_A: 0.22; AEC Category: Q101
Q12 = MMBT2907A, Fairchild Semiconductor: Transistor, PNP, 60 V, 0.8 A, SOT-23; CompType: BJT; PNP: 1; NPN: 0; Vceo_V: 60; Vcesat1_V: 1.6; Value: 60 V; IcRated_A: 0.8; Value1: 0.8 A; HfeMax: 300; TaMin_C: -55; TaMax_C: 150; U/M: EA
R1 = CRCW08052R21FKEA: RES, 2.21, 1%, 0.125 W, 0805; Manufacturer: Vishay-Dale; CompType: Resistor; Value: 2.21; Value_Code: 2R21; Tolerance_%: 1; Power_W: 0.125; Value2: 0.125W; VDC_V: 150; TempCo: 100 ppm/C; EIA_Code: E96; U/M: EA; AEC Category: Q200
R2 = RC1206FR-072R2L: RES, 2.20 ohm, 1%, 0.25W, 1206; Manufacturer: Yageo America; CompType: Resistor; Res_ohm: 2.2; Value_Code: 2R20; Tolerance_%: 1; Power_W: 0.25; VDC_V: 200; TempCo: 200 ppm/C; U/M: EA
R3 = CRCW0603100RFKEA: RES, 100, 1%, 0.1 W, 0603; Manufacturer: Vishay-Dale; CompType: Resistor; Value: 100; Value_Code: 100R; Tolerance_%: 1; Power_W: 0.1; Value2: 0.1W; VDC_V: 75; TempCo: 100 ppm/C; EIA_Code: E96; U/M: EA; AEC Category: Q200
R4 = CRCW060329K4FKEA: RES, 29.4 k, 1%, 0.1 W, 0603; Manufacturer: Vishay-Dale; CompType: Resistor; Value: 29.4k; Res_ohm: 29400; Value_Code: 29k4; Tolerance_%: 1; Power_W: 0.1; Value2: 0.1W; VDC_V: 75; TempCo: 100 ppm/C; EIA_Code: E96; U/M: EA; AEC Category: Q200
R5 R6 R9 R12 = CRCW251268R1FKEG: RES, 68.1, 1%, 1 W, 2512; Manufacturer: Vishay-Dale; CompType: Resistor; Value: 68.1; Value_Code: 68R1; Tolerance_%: 1; Value2: 1W; VDC_V: 500; TempCo: 100 ppm/C; EIA_Code: E96; U/M: EA; AEC Category: Q200
R7 R10 = RC0805FR-074R75L: RES, 4.75, 1%, 0.125 W, 0805; Manufacturer: Yageo America; CompType: Resistor; Value: 4.75; Value_Code: 4R75; Tolerance_%: 1; Power_W: 0.125; Value2: 0.125W; VDC_V: 150; TempCo: 200 ppm/C; SizeArea_mm2: 2.5; SizeX_mm: 2; SizeY_mm: 1.25; SizeZ_mm: 1.45; EIA_Code: E96; U/M: EA; AEC Category: Q200
R8 R13 = CRCW060310K0FKEA: RES, 10.0k ohm, 1%, 0.1W, 0603; Manufacturer: Vishay-Dale; Alternate Manufacturer: Any; Alternate PartNumber: Equivalent; CompType: Resistor; Res_ohm: 10000; Value_Code: 10k0; Tolerance_%: 1; Power_W: 0.1; VDC_V: 75; TempCo: 100 ppm/C; EIA_Code: E96; U/M: EA
R11 R17 R53 = CRCW06031K00FKEA: RES, 1.00 k, 1%, 0.1 W, 0603; Manufacturer: Vishay-Dale; CompType: Resistor; Value: 1.00k; Res_ohm: 1000; Value_Code: 1k00; Tolerance_%: 1; Power_W: 0.1; Value2: 0.1W; VDC_V: 75; TempCo: 100 ppm/C; EIA_Code: E96; U/M: EA
R14 = CSR2512FG68L0: RES, 0.068, 1%, 2 W, 2512; Manufacturer: TE Connectivity; CompType: Resistor; Value: 0.068; Value_Code: R068; Tolerance_%: 1; Power_W: 2; Value2: 2W; TempCo: 200 ppm/C; U/M: EA
R15 = CRCW06034K75FKEA: RES, 4.75 k, 1%, 0.1 W, 0603; Manufacturer: Vishay-Dale; CompType: Resistor; Value: 4.75k; Res_ohm: 4750; Value_Code: 4k75; Tolerance_%: 1; Power_W: 0.1; Value2: 0.1W; VDC_V: 75; TempCo: 100 ppm/C; EIA_Code: E96; U/M: EA; AEC Category: Q200
R16 = CRCW12064K75FKEA: RES, 4.75 k, 1%, 0.25 W, 1206; Manufacturer: Vishay-Dale; CompType: Resistor; Value: 4.75k; Res_ohm: 4750; Value_Code: 4k75; Tolerance_%: 1; Power_W: 0.25; Value2: 0.25W; VDC_V: 200; TempCo: 100 ppm/C; EIA_Code: E96; U/M: EA; AEC Category: Q200
R18 R19 = CRCW06031K00FKEA: RES, 1.00 k, 1%, 0.1 W, 0603; Manufacturer: Vishay-Dale; CompType: Resistor; Value: 1.00k; Res_ohm: 1000; Value_Code: 1k00; Tolerance_%: 1; Power_W: 0.1; Value2: 0.1W; VDC_V: 75; TempCo: 100 ppm/C; EIA_Code: E96; U/M: EA; AEC Category: Q200
R20 = CRCW1206698KFKEA: RES, 698k ohm, 1%, 0.25W, 1206; Manufacturer: Vishay-Dale; CompType: Resistor; Res_ohm: 698000; Tolerance_%: 1; Power_W: 0.25; VDC_V: 200; TempCo: 100 ppm/C; EIA_Code: E96; U/M: EA
R21 = CRCW060323K7FKEA: RES, 23.7 k, 1%, 0.1 W, 0603; Manufacturer: Vishay-Dale; CompType: Resistor; Value: 23.7k; Res_ohm: 23700; Value_Code: 23k7; Tolerance_%: 1; Power_W: 0.1; Value2: 0.1W; VDC_V: 75; TempCo: 100 ppm/C; EIA_Code: E96; U/M: EA
R22 = CRCW06033K32FKEA: RES, 3.32 k, 1%, 0.1 W, 0603; Manufacturer: Vishay-Dale; CompType: Resistor; Value: 3.32k; Res_ohm: 3320; Value_Code: 3k32; Tolerance_%: 1; Power_W: 0.1; Value2: 0.1W; VDC_V: 75; TempCo: 100 ppm/C; EIA_Code: E96; U/M: EA; AEC Category: Q200
R23 = CRCW06032K21FKEA: RES, 2.21k ohm, 1%, 0.1W, 0603; Manufacturer: Vishay-Dale; CompType: Resistor; Res_ohm: 2210; Value_Code: 2k21; Tolerance_%: 1; Power_W: 0.1; VDC_V: 75; TempCo: 100 ppm/C; EIA_Code: E96; U/M: EA
R24 = CRCW201068K1FKEF: RES, 68.1 k, 1%, 0.75 W, 2010; Manufacturer: Vishay-Dale; CompType: Resistor; Value: 68.1k; Res_ohm: 68100; Value_Code: 68k1; Tolerance_%: 1; Power_W: 0.75; Value2: 0.75W; VDC_V: 400; TempCo: 100 ppm/C; EIA_Code: E96; U/M: EA; AEC Category: Q200
R25 R29 = CRCW1206715KFKEA: RES, 715k ohm, 1%, 0.25W, 1206; Manufacturer: Vishay-Dale; CompType: Resistor; Res_ohm: 715000; Tolerance_%: 1; Power_W: 0.25; VDC_V: 200; TempCo: 100 ppm/C; EIA_Code: E96; U/M: EA
R26 = CRCW060316K5FKEA: RES, 16.5 k, 1%, 0.1 W, 0603; Manufacturer: Vishay-Dale; CompType: Resistor; Value: 16.5k; Res_ohm: 16500; Value_Code: 16k5; Tolerance_%: 1; Power_W: 0.1; Value2: 0.1W; VDC_V: 75; TempCo: 100 ppm/C; EIA_Code: E96; U/M: EA
R27 R33 = CRCW060368K1FKEA: RES, 68.1 k, 1%, 0.1 W, 0603; Manufacturer: Vishay-Dale; CompType: Resistor; Value: 68.1k; Res_ohm: 68100; Value_Code: 68k1; Tolerance_%: 1; Power_W: 0.1; Value2: 0.1W; VDC_V: 75; TempCo: 100 ppm/C; EIA_Code: E96; U/M: EA; AEC Category: Q200
R28 = CRCW251233R2FKEG: RES, 33.2, 1%, 1 W, 2512; Manufacturer: Vishay-Dale; CompType: Resistor; Value: 33.2; Value_Code: 33R2; Tolerance_%: 1; Value2: 1W; VDC_V: 500; TempCo: 100 ppm/C; EIA_Code: E96; U/M: EA; AEC Category: Q200
R30 = CRCW06031M21FKEA: RES, 1.21 M, 1%, 0.1 W, 0603; Manufacturer: Vishay-Dale; CompType: Resistor; Value: 1.21Meg; Res_ohm: 1210000; Value_Code: 1M21; Tolerance_%: 1; Power_W: 0.1; Value2: 0.1W; VDC_V: 75; TempCo: 100 ppm/C; EIA_Code: E96; U/M: EA; AEC Category: Q200
R31 R39 = CRCW060347K5FKEA: RES, 47.5 k, 1%, 0.1 W, 0603; Manufacturer: Vishay-Dale; CompType: Resistor; Value: 47.5k; Res_ohm: 47500; Value_Code: 47k5; Tolerance_%: 1; Power_W: 0.1; Value2: 0.1W; VDC_V: 75; TempCo: 100 ppm/C; EIA_Code: E96; U/M: EA; AEC Category: Q200
R32 = CRCW060349R9FKEA: RES, 49.9 ohm, 1%, 0.1W, 0603; Manufacturer: Vishay-Dale; CompType: Resistor; Value_Code: 49R9; Tolerance_%: 1; Power_W: 0.1; VDC_V: 75; TempCo: 100 ppm/C; EIA_Code: E96; U/M: EA
R34 = CRCW060361K9FKEA: RES, 61.9 k, 1%, 0.1 W, 0603; Manufacturer: Vishay-Dale; CompType: Resistor; Value: 61.9k; Res_ohm: 61900; Value_Code: 61k9; Tolerance_%: 1; Power_W: 0.1; Value2: 0.1W; VDC_V: 75; TempCo: 100 ppm/C; SizeArea_mm2: 1.28; SizeX_mm: 1.6; SizeY_mm: 0.8; EIA_Code: E96; U/M: EA; AEC Category: Q200
R35 = CRCW0603221KFKEA: RES, 221 k, 1%, 0.1 W, 0603; Manufacturer: Vishay-Dale; CompType: Resistor; Value: 221k; Res_ohm: 221000; Tolerance_%: 1; Power_W: 0.1; Value2: 0.1W; VDC_V: 75; TempCo: 100 ppm/C; EIA_Code: E96; U/M: EA; AEC Category: Q200
R36 R41 R43 R51 R67 = CRCW060310K0FKEA: RES, 10.0k ohm, 1%, 0.1W, 0603; Manufacturer: Vishay-Dale; CompType: Resistor; Res_ohm: 10000; Value_Code: 10k0; Tolerance_%: 1; Power_W: 0.1; VDC_V: 75; TempCo: 100 ppm/C; EIA_Code: E96; U/M: EA
R37 = RC0603FR-0715KL: RES, 15.0 k, 1%, 0.1 W, 0603; Manufacturer: Yageo America; CompType: Resistor; Value: 15.0k; Res_ohm: 15000; Value_Code: 15k0; Tolerance_%: 1; Power_W: 0.1; Value2: 0.1W; VDC_V: 150; TempCo: 200 ppm/C; SizeArea_mm2: 1.28; SizeX_mm: 1.6; SizeY_mm: 0.8; EIA_Code: E96; U/M: EA; AEC Category: Q200
R38 = CRCW06036K81FKEA: RES, 6.81k ohm, 1%, 0.1W, 0603; Manufacturer: Vishay-Dale; CompType: Resistor; Res_ohm: 6810; Value_Code: 6k81; Tolerance_%: 1; Power_W: 0.1; VDC_V: 75; TempCo: 100 ppm/C; EIA_Code: E96; U/M: EA
R40 R42 R47 R50 = CRCW0603100KFKEA: RES, 100 k, 1%, 0.1 W, 0603; Manufacturer: Vishay-Dale; CompType: Resistor; Value: 100k; Res_ohm: 100000; Tolerance_%: 1; Power_W: 0.1; Value2: 0.1W; VDC_V: 75; TempCo: 100 ppm/C; EIA_Code: E96; U/M: EA
R44 = RC0603FR-0747K5L: RES, 47.5 k, 1%, 0.1 W, 0603; Manufacturer: Yageo America; CompType: Resistor; Value: 47.5k; Res_ohm: 47500; Value_Code: 47k5; Tolerance_%: 1; Power_W: 0.1; Value2: 0.1W; VDC_V: 150; TempCo: 200 ppm/C; SizeArea_mm2: 1.28; SizeX_mm: 1.6; SizeY_mm: 0.8; EIA_Code: E96; U/M: EA; AEC Category: Q200
R45 R46 R54 = CRCW0603100RFKEA: RES, 100, 1%, 0.1 W, 0603; Manufacturer: Vishay-Dale; CompType: Resistor; Value: 100; Value_Code: 100R; Tolerance_%: 1; Power_W: 0.1; Value2: 0.1W; VDC_V: 75; TempCo: 100 ppm/C; SizeArea_mm2: 1.28; SizeX_mm: 1.6; SizeY_mm: 0.8; EIA_Code: E96; U/M: EA; AEC Category: Q200
R48 = RC0603FR-0713KL: RES, 13.0 k, 1%, 0.1 W, 0603; Manufacturer: Yageo America; CompType: Resistor; Value: 13.0k; Res_ohm: 13000; Value_Code: 13k0; Tolerance_%: 1; Power_W: 0.1; Value2: 0.1W; VDC_V: 150; TempCo: 200 ppm/C; SizeArea_mm2: 1.28; SizeX_mm: 1.6; SizeY_mm: 0.8; EIA_Code: E96; U/M: EA; AEC Category: Q200
R49 = RC0603FR-07475KL: RES, 475 k, 1%, 0.1 W, 0603; Manufacturer: Yageo America; CompType: Resistor; Value: 475k; Res_ohm: 475000; Tolerance_%: 1; Power_W: 0.1; Value2: 0.1W; VDC_V: 150; TempCo: 200 ppm/C; SizeArea_mm2: 1.28; SizeX_mm: 1.6; SizeY_mm: 0.8; EIA_Code: E96; U/M: EA; AEC Category: Q200
R52 = CRCW060333K2FKEA: RES, 33.2 k, 1%, 0.1 W, 0603; Manufacturer: Vishay-Dale; CompType: Resistor; Value: 33.2k; Res_ohm: 33200; Value_Code: 33k2; Tolerance_%: 1; Power_W: 0.1; Value2: 0.1W; VDC_V: 75; TempCo: 100 ppm/C; EIA_Code: E96; U/M: EA; AEC Category: Q200
R68 = CRCW06031R00FKEA: RES, 0 Ohm, 1%, 0.1 W, 0603; Manufacturer: Vishay-Dale; CompType: Resistor; Res_ohm: 1; Power_W: 0.1; Value2: 0.1W; VDC_V: 75; TempCo: 100 ppm/C; SizeArea_mm2: 1.28; SizeX_mm: 1.6; SizeY_mm: 0.8; EIA_Code: E96; U/M: EA; AEC Category: Q200
S1 = 200USP1T1A1M2RE: Switch, SPDT, On-On, 2 Pos, TH; Manufacturer: E-Switch; SymbolCreator: Altium; VDC_V: 20; PositionCount: 2; CurrentRating_mA: 400
T1 = 750315800: Transformer, 2 mH, TH; Manufacturer: Wurth Elektronik; SymbolCreator: Altium; Value: 2mH; Lp: 2000; DCR_ohm: 0.2; LeakageL: 37; Ns1toNp: 0.25; Rs1: 0.03; SizeAreaWB_mm2: 1477.6104; SizeArea_mm2: 1327.8104; SizeX_mm: 37.34; SizeY_mm: 35.56; SizeZ_mm: 34.29
TP2 TP5-TP8 TP10 = PAD_115mil-80milhole: 115mil pad, 80mil hole; Manufacturer: Any
TP3 = 5000: Test Point, Miniature, Red, TH; Manufacturer: Keystone; CompType: Test Point Loop; U/M: EA
TP4 = 5001: Test Point, Miniature, Black, TH; Manufacturer: Keystone; CompType: Test Point Loop; U/M: EA
TP9 = 5003: Test Point, Miniature, Orange, TH; Manufacturer: Keystone; CompType: Test Point Loop; U/M: EA
U1 = DS90LT012AHMF/NOPB: Resistor-Programmable Temperature Switch, 5 pin SOT-23; PartNumber: TMP709AIDBVR; Manufacturer: Texas Instruments; PowerWise: N
U2 = UCC27714DR: High-Speed,4A, 600V High-side Low-side Gate Driver Device, D0014A; Manufacturer: Texas Instruments; SymbolCreator: a0411947; CompType: IC; U/M: EA
U3 = SN74LVC1G17DCKR: SINGLE SCHMITT-TRIGGER BUFFER, DCK0005A; Alternate PartNumber: SN74LVC1G17DCKT; Manufacturer: Texas Instruments; SymbolCreator: a0799628; CompType: IC; U/M: EA
U4 = LM5021MMX-2: AC-DC Current Mode PWM Controller, 8-pin MSOP; PartNumber: LM5021MM-2/NOPB; Manufacturer: Texas Instruments; PackageTopMarking: ZXTT*21-2; PowerWise: N; CompType: Switcher
U5 U8 = TCMT1107: Optocoupler, 3.75 kV, 80-160% CTR, SMD-4; Manufacturer: Vishay-Semiconductor; CTR_Min: 80% @ 5mA; CTR_Max: 160% @ 5mA; Voltage_Isolation_Vrms: 3750; tr_typ: 4us; tf_typ: 4.7us; U/M: EA
U6 = TL431AIDBZR: Adjustable Precision Shunt Regulator, 34 ppm / degC, 100 mA, -40 to 85 degC, 3-pin SOT-23 (DBZ), Green (RoHS & no Sb/Br); Manufacturer: Texas Instruments; Alternate PartNumber: Equivalent; Initial Accuracy @ 25/deg C(%): 1; Iout/Iz(Max)(mA): 100; Min Iz for Regulation(uA): 600; Rating: Catalog; SubFamily: Shunt Voltage Reference; Temp Coeff(Max)(ppm/ degree C): 92; Temp Coeff(Typ)(ppm/ degree C): 34; VO Adj(Max)(V): 36; VO Adj(Min)(V): 2.495
U7 = LMV431AIMF: Low-Voltage (1.24V) Adjustable Precision Shunt Regulator, 3-pin SOT-23; PartNumber: LMV431AIMFX/NOPB; Manufacturer: Texas Instruments; PackageTopMarking: RLA*XTT; PowerWise: N; CompType: MiscPower

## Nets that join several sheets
EARTH: PMP30183 Rev_B PFC Boost + Aux Schematic (C34.1 C60.2 TP1.1), PMP30183 Rev_B 2-Switch Forward Schematic (C14.1 TP5.1 TP8.1)
PGND: PMP30183 Rev_B PFC Boost + Aux Schematic (32 pins), PMP30183 Rev_B 2-Switch Forward Schematic (29 pins)
SGND: PMP30183 Rev_B PFC Boost + Aux Schematic (12 pins), PMP30183 Rev_B 2-Switch Forward Schematic (39 pins)
+3.3Vsec: PMP30183 Rev_B PFC Boost + Aux Schematic (5 pins), PMP30183 Rev_B 2-Switch Forward Schematic (R3.2 R54.1 R67.2 S1.6)
+12V switched: PMP30183 Rev_B PFC Boost + Aux Schematic (C45.1 Q17.3 U9.7), PMP30183 Rev_B 2-Switch Forward Schematic (R1.1 R11.2)
+12Vsec: PMP30183 Rev_B PFC Boost + Aux Schematic (7 pins), PMP30183 Rev_B 2-Switch Forward Schematic (Q11.2 R41.1)
+24V switched: PMP30183 Rev_B PFC Boost + Aux Schematic (Q17.2 Q17.4 R70.1), PMP30183 Rev_B 2-Switch Forward Schematic (7 pins)
+24Vprim: PMP30183 Rev_B PFC Boost + Aux Schematic (C50.1 D33.1 D35.1), PMP30183 Rev_B 2-Switch Forward Schematic (Q12.2 R50.2)
+400V: PMP30183 Rev_B PFC Boost + Aux Schematic (9 pins), PMP30183 Rev_B 2-Switch Forward Schematic (J1.1 R20.2)

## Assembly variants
001: not fitted FID1 FID2 R153 R156 TP125 TP126 TP127 TP128 TP129 TP130 TP131
Variant of PMP8529 RevB: all parts fitted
